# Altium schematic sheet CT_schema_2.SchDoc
size 523 x 486 mm
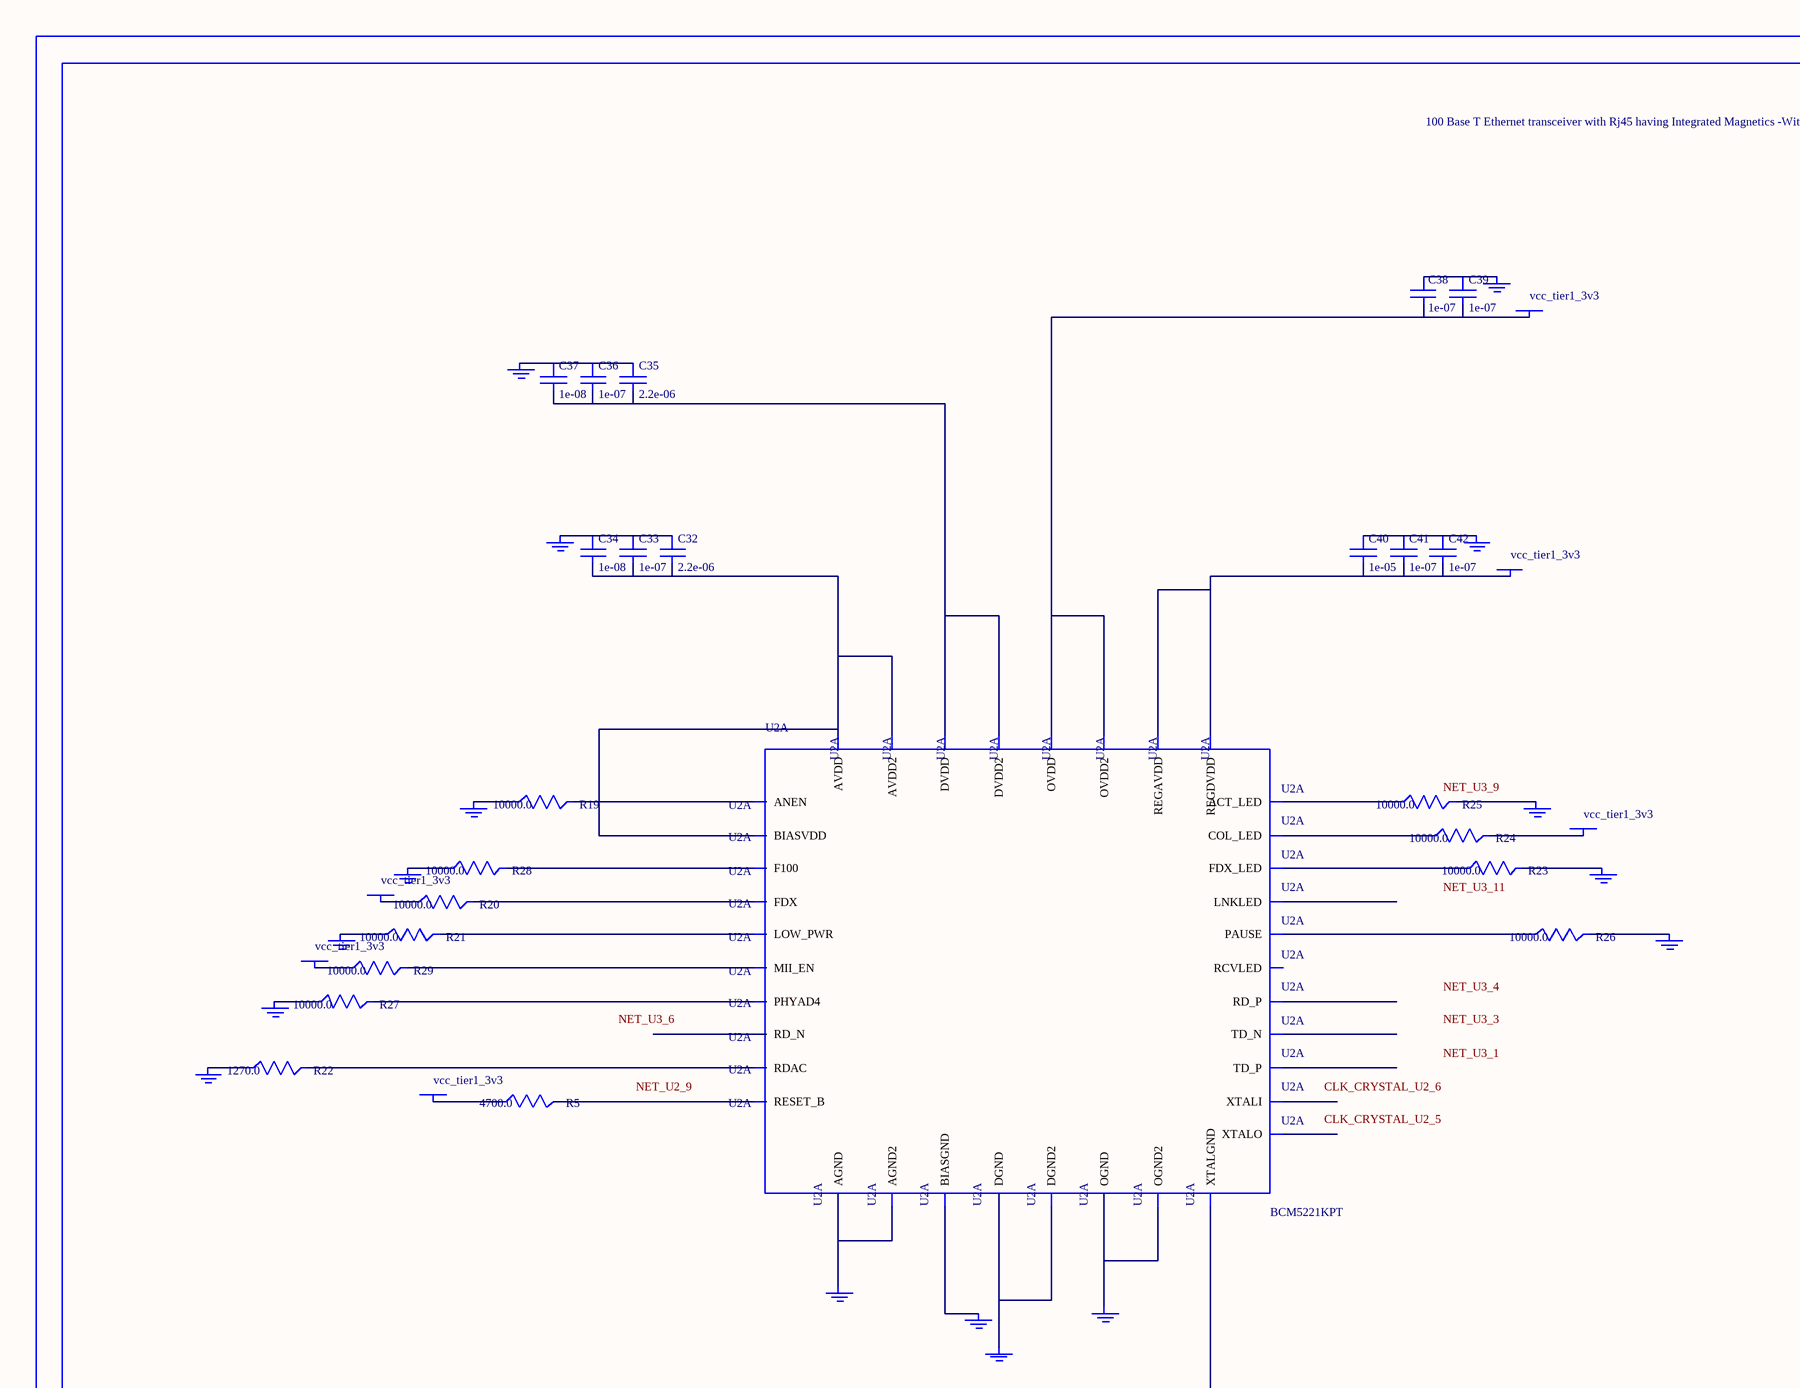
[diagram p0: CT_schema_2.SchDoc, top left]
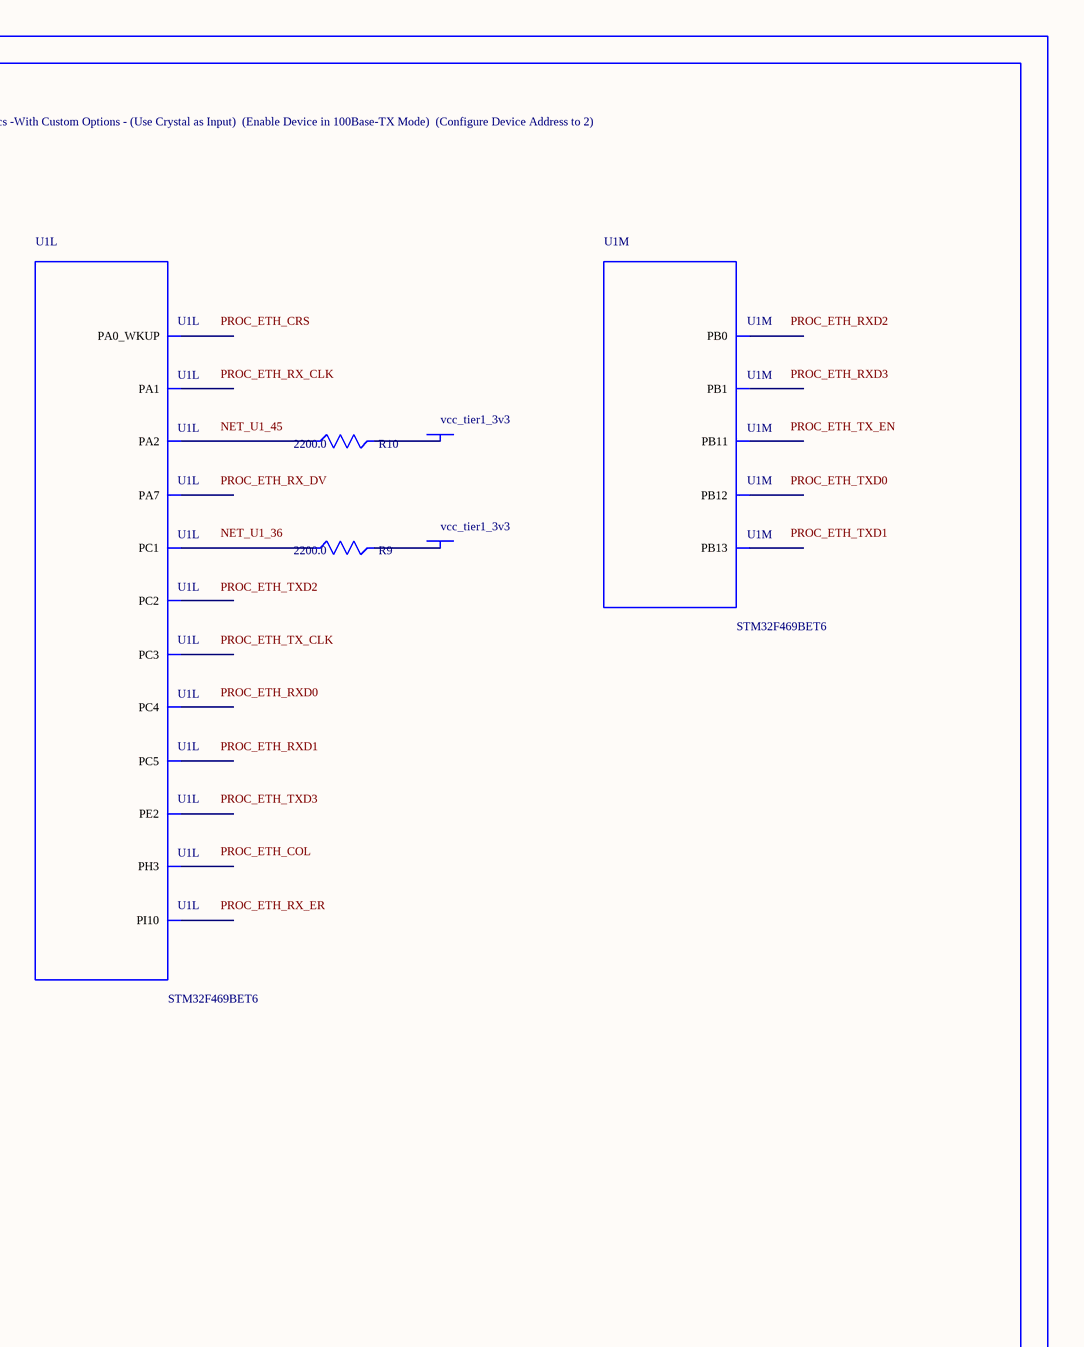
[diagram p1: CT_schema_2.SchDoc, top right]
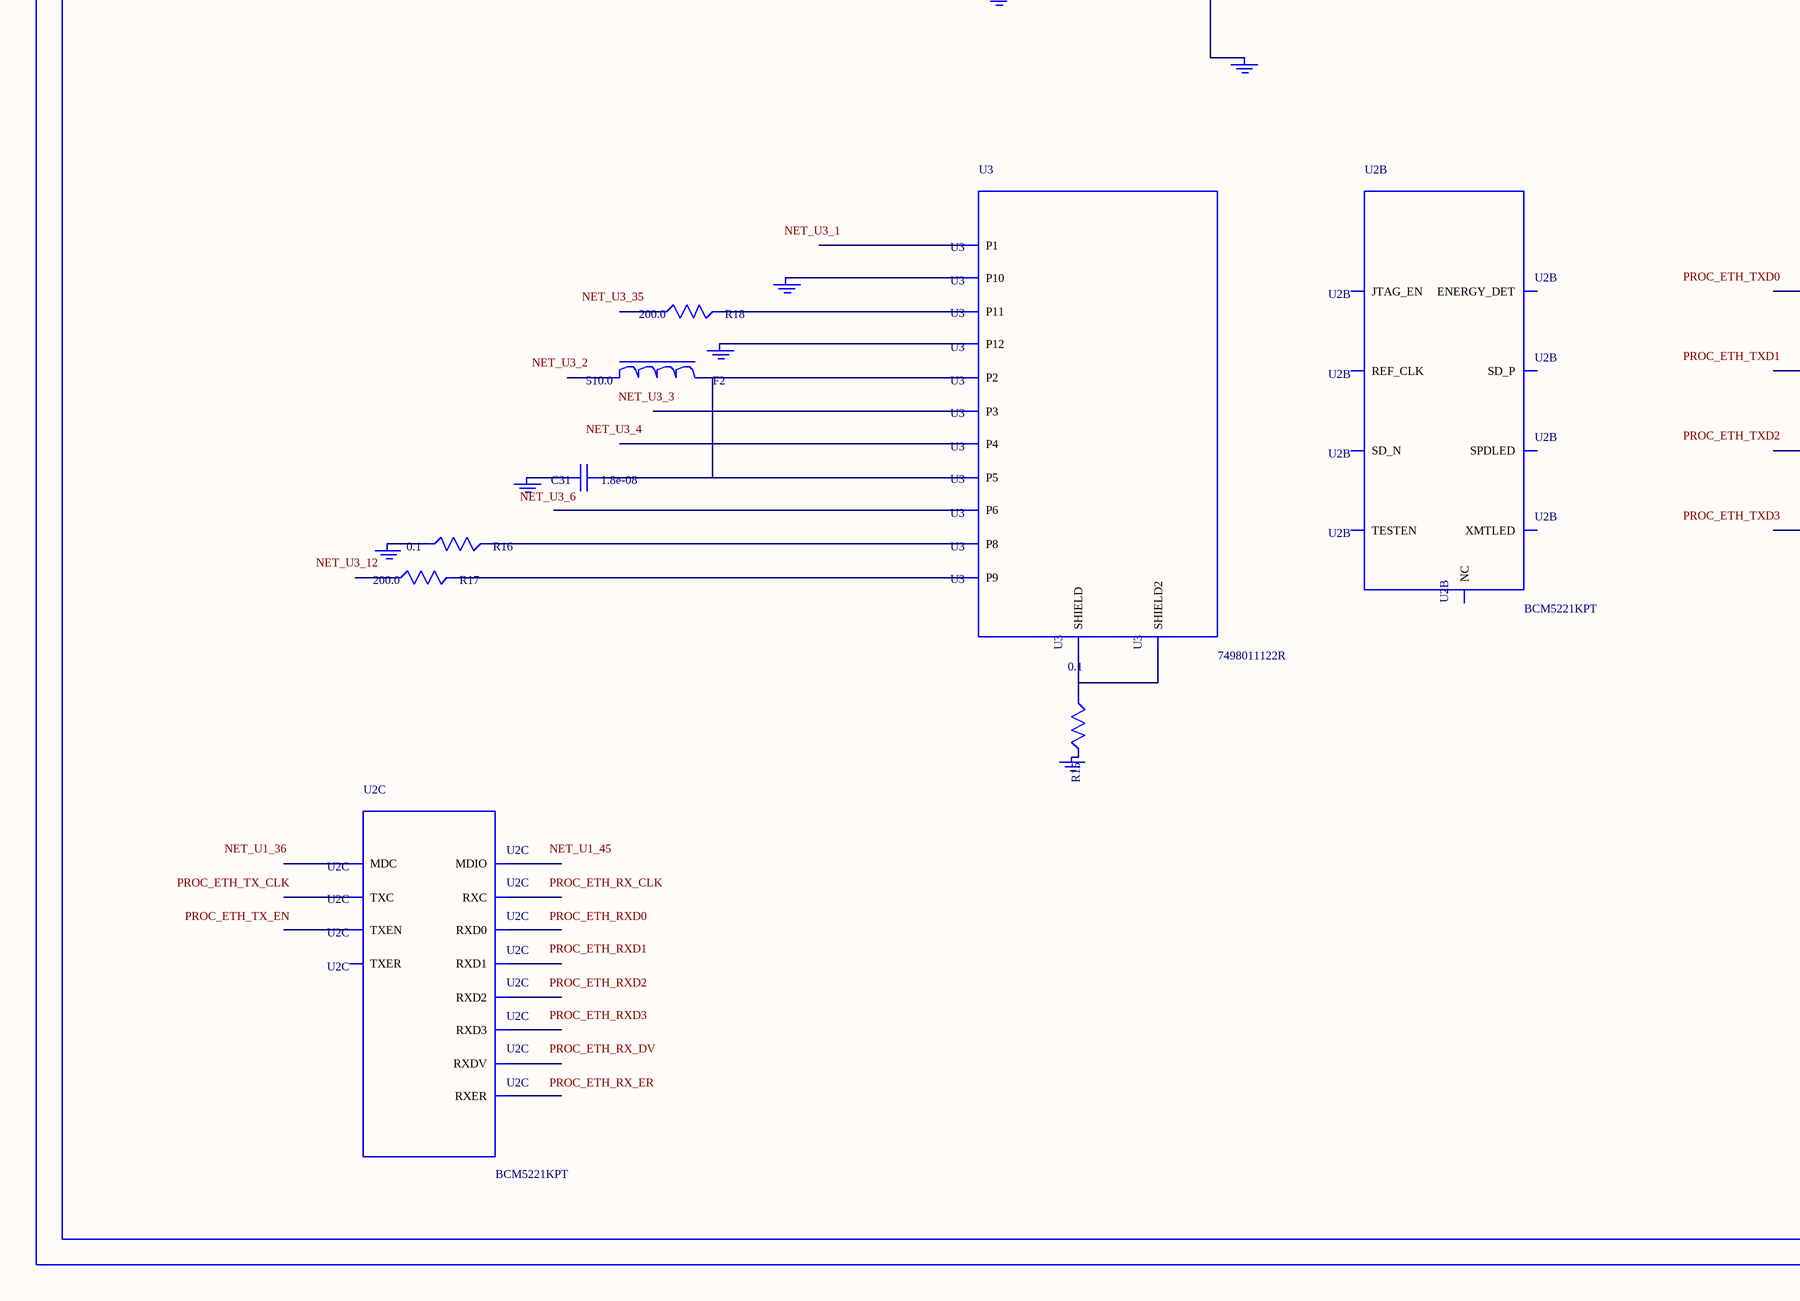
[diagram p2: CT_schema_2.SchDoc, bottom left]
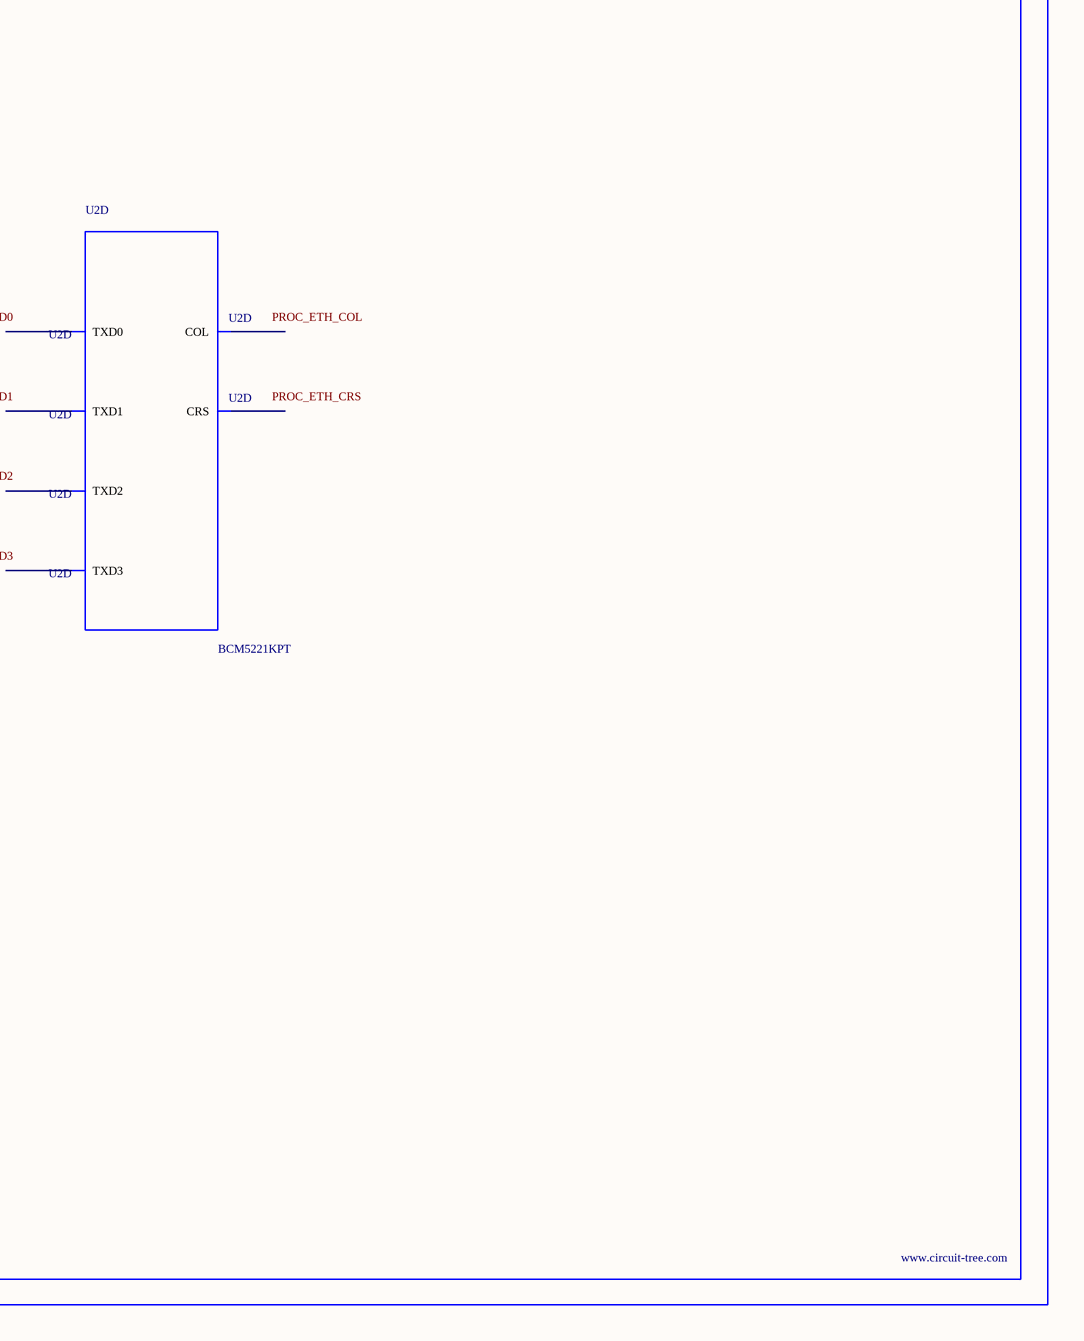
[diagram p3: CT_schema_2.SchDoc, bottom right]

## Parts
BORDER1  (no value)
C31  1.8e-08  [C0402]
C32  2.2e-06  [C0603]
C33  1e-07  [C0402]
C34  1e-08  [C0402]
C35  2.2e-06  [C0603]
C36  1e-07  [C0402]
C37  1e-08  [C0402]
C38  1e-07  [C0402]
C39  1e-07  [C0402]
C40  1e-05  [C0805]
C41  1e-07  [C0402]
C42  1e-07  [C0402]
F2  510.0  [L0603]
GND_INSTANCE_1_0  (no value)
GND_INSTANCE_1_1  (no value)
GND_INSTANCE_1_2  (no value)
GND_INSTANCE_1_3  (no value)
GND_INSTANCE_1_4  (no value)
GND_INSTANCE_1_5  (no value)
GND_INSTANCE_1_6  (no value)
GND_INSTANCE_1_7  (no value)
GND_INSTANCE_1_8  (no value)
GND_INSTANCE_1_9  (no value)
GND_INSTANCE_1_10  (no value)
GND_INSTANCE_1_11  (no value)
GND_INSTANCE_1_12  (no value)
GND_INSTANCE_1_13  (no value)
GND_INSTANCE_1_14  (no value)
GND_INSTANCE_1_15  (no value)
GND_INSTANCE_1_16  (no value)
GND_INSTANCE_1_17  (no value)
GND_INSTANCE_1_18  (no value)
GND_INSTANCE_1_19  (no value)
GND_INSTANCE_1_20  (no value)
GND_INSTANCE_1_21  (no value)
POWER_INSTANCE_1_0  vcc_tier1_3v3
POWER_INSTANCE_1_1  vcc_tier1_3v3
POWER_INSTANCE_1_2  vcc_tier1_3v3
POWER_INSTANCE_1_3  vcc_tier1_3v3
POWER_INSTANCE_1_4  vcc_tier1_3v3
POWER_INSTANCE_1_5  vcc_tier1_3v3
POWER_INSTANCE_1_6  vcc_tier1_3v3
POWER_INSTANCE_1_7  vcc_tier1_3v3
R5  4700.0  [R0603]
R9  2200.0  [R0603]
R10  2200.0  [R0603]
R15  0.1  [R0603]
R16  0.1  [R0603]
R17  200.0  [R0603]
R18  200.0  [R0603]
R19  10000.0  [R0603]
R20  10000.0  [R0603]
R21  10000.0  [R0603]
R22  1270.0  [R0603]
R23  10000.0  [R0603]
R24  10000.0  [R0603]
R25  10000.0  [R0603]
R26  10000.0  [R0603]
R27  10000.0  [R0603]
R28  10000.0  [R0603]
R29  10000.0  [R0603]
U1  STM32F469BET6  [LQFP208]  (parts L,M of 18)
U2  BCM5221KPT  [TQFP64_10X10MC]  (parts A,B,C,D of 4)
U3  7498011122R  [7498011122R]

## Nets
NetC31_1: C31.1 F2.2 U3.2(P2) U3.5(P5)
NetC31_2: C31.2 GND_INSTANCE_1_17.0(GND)
NetC32_1: C32.1 C33.1 C34.1 GND_INSTANCE_1_11.0(GND)
NetC32_2: C32.2 C33.2 C34.2 U2.22(BIASVDD) U2.27(AVDD) U2.28(AVDD2)
NetC35_1: C35.1 C36.1 C37.1 GND_INSTANCE_1_1.0(GND)
NetC35_2: C35.2 C36.2 C37.2 U2.2(DVDD) U2.55(DVDD2)
NetC38_1: C38.1 C39.1 GND_INSTANCE_1_0.0(GND)
NetC38_2: C38.2 C39.2 POWER_INSTANCE_1_0.0(PWR) U2.1(OVDD) U2.46(OVDD2)
NetC40_1: C40.1 C41.1 C42.1 GND_INSTANCE_1_2.0(GND)
NetC40_2: C40.2 C41.2 C42.2 POWER_INSTANCE_1_1.0(PWR) U2.3(REGDVDD) U2.20(REGAVDD)
NetGND_INSTANCE_1_3_0: GND_INSTANCE_1_3.0(GND) U2.7(XTALGND)
NetGND_INSTANCE_1_4_0: GND_INSTANCE_1_4.0(GND) R23.2
NetGND_INSTANCE_1_5_0: GND_INSTANCE_1_5.0(GND) R25.2
NetGND_INSTANCE_1_6_0: GND_INSTANCE_1_6.0(GND) R26.2
NetGND_INSTANCE_1_7_0: GND_INSTANCE_1_7.0(GND) R27.1
NetGND_INSTANCE_1_8_0: GND_INSTANCE_1_8.0(GND) R21.1
NetGND_INSTANCE_1_9_0: GND_INSTANCE_1_9.0(GND) R22.1
NetGND_INSTANCE_1_10_0: GND_INSTANCE_1_10.0(GND) U2.24(BIASGND)
NetGND_INSTANCE_1_12_0: GND_INSTANCE_1_12.0(GND) R28.1
NetGND_INSTANCE_1_13_0: GND_INSTANCE_1_13.0(GND) R19.1
NetGND_INSTANCE_1_14_0: GND_INSTANCE_1_14.0(GND) U2.29(AGND) U2.32(AGND2)
NetGND_INSTANCE_1_15_0: GND_INSTANCE_1_15.0(GND) U2.40(OGND) U2.45(OGND2)
NetGND_INSTANCE_1_16_0: GND_INSTANCE_1_16.0(GND) U2.54(DGND) U2.63(DGND2)
NetGND_INSTANCE_1_18_0: GND_INSTANCE_1_18.0(GND) R16.1
NetGND_INSTANCE_1_19_0: GND_INSTANCE_1_19.0(GND) U3.10(P10)
NetGND_INSTANCE_1_20_0: GND_INSTANCE_1_20.0(GND) U3.12(P12)
NetGND_INSTANCE_1_21_0: GND_INSTANCE_1_21.0(GND) R15.2
NetPOWER_INSTANCE_1_2_0: POWER_INSTANCE_1_2.0(PWR) R24.2
NetPOWER_INSTANCE_1_3_0: POWER_INSTANCE_1_3.0(PWR) R29.1
NetPOWER_INSTANCE_1_4_0: POWER_INSTANCE_1_4.0(PWR) R20.1
NetPOWER_INSTANCE_1_5_0: POWER_INSTANCE_1_5.0(PWR) R5.1
NetPOWER_INSTANCE_1_6_0: POWER_INSTANCE_1_6.0(PWR) R9.2
NetPOWER_INSTANCE_1_7_0: POWER_INSTANCE_1_7.0(PWR) R10.2
NetR5_2: R5.2 U2.9(RESET_B)
NetR9_1: R9.1 U1.36(PC1)
NetR10_1: R10.1 U1.45(PA2)
NetR15_1: R15.1 U3.13(SHIELD) U3.14(SHIELD2)
NetR16_2: R16.2 U3.8(P8)
NetR17_2: R17.2 U3.9(P9)
NetR18_2: R18.2 U3.11(P11)
NetR19_2: R19.2 U2.38(ANEN)
NetR20_2: R20.2 U2.39(FDX)
NetR21_2: R21.2 U2.16(LOW_PWR)
NetR22_2: R22.2 U2.23(RDAC)
NetR23_1: R23.1 U2.10(FDX_LED)
NetR24_1: R24.1 U2.11(COL_LED)
NetR25_1: R25.1 U2.12(ACT_LED)
NetR26_1: R26.1 U2.13(PAUSE)
NetR27_2: R27.2 U2.14(PHYAD4)
NetR28_2: R28.2 U2.37(F100)
NetR29_2: R29.2 U2.18(MII_EN)

Not connected (* = marked no-connect by the designer): F2 1; R17 1; R18 1; U1 1(PE2) 12(PI10) 37(PC2) 38(PC3) 43(PA0_WKUP) 44(PA1) 47(PH3) 56(PA7) 57(PC4) 58(PC5) 61(PB0) 62(PB1) 91(PB11) 104(PB12) 105(PB13); U2 4(REF_CLK) 5(XTALO) 6(XTALI) 8(NC) 15(TESTEN) 17(ENERGY_DET) 19(SD_N) 21(SD_P) 25(RD_N) 26(RD_P) 30(TD_N) 31(TD_P) 33(RCVLED) 34(XMTLED) 35(LNKLED) 36(SPDLED) 41(MDIO) 42(MDC) 43(RXD3) 44(RXD2) 47(RXD1) 48(RXD0) 49(RXDV) 50(RXC) 51(RXER) 52(TXER) 53(TXC) 56(TXEN) 57(TXD0) 58(TXD1) 59(TXD2) 60(TXD3) 61(COL) 62(CRS) 64(JTAG_EN); U3 1(P1) 3(P3) 4(P4) 6(P6)

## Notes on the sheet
- Labels drawn without touching a wire or pin: CLK_CRYSTAL_U2_5, CLK_CRYSTAL_U2_6, NET_U1_36, NET_U1_45, NET_U2_9, NET_U3_1, NET_U3_2, NET_U3_3, NET_U3_4, NET_U3_6, NET_U3_9, NET_U3_11, NET_U3_12, NET_U3_35, PROC_ETH_COL, PROC_ETH_CRS, PROC_ETH_RX_CLK, PROC_ETH_RX_DV, PROC_ETH_RX_ER, PROC_ETH_RXD0, PROC_ETH_RXD1, PROC_ETH_RXD2, PROC_ETH_RXD3, PROC_ETH_TX_CLK, PROC_ETH_TX_EN, PROC_ETH_TXD0, PROC_ETH_TXD1, PROC_ETH_TXD2, PROC_ETH_TXD3

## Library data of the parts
BORDER1 = BORDER_PAGE1
C31 = C0402C183K3RAC
C32 C35 = C0603C225K8RACTU
C33 C36 C38 C39 C41 C42 = C0402C104K3RACTU
C34 C37 = C0402C103K3RAC
C40 = C0805C106K8RACTU
F2 = ERA3APB511V
GND_INSTANCE_1_0-GND_INSTANCE_1_21 = GND
POWER_INSTANCE_1_0-POWER_INSTANCE_1_7 = PWR
R5 = RC0603JR-074K7L
R9 R10 = RC0603JR-072K2L
R15 R16 = ERJ-3RSFR10V
R17 R18 = RC0603JR-07200RL
R19-R21 R23-R29 = RC0603JR-0710KL
R22 = RC0603FR-071K27L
